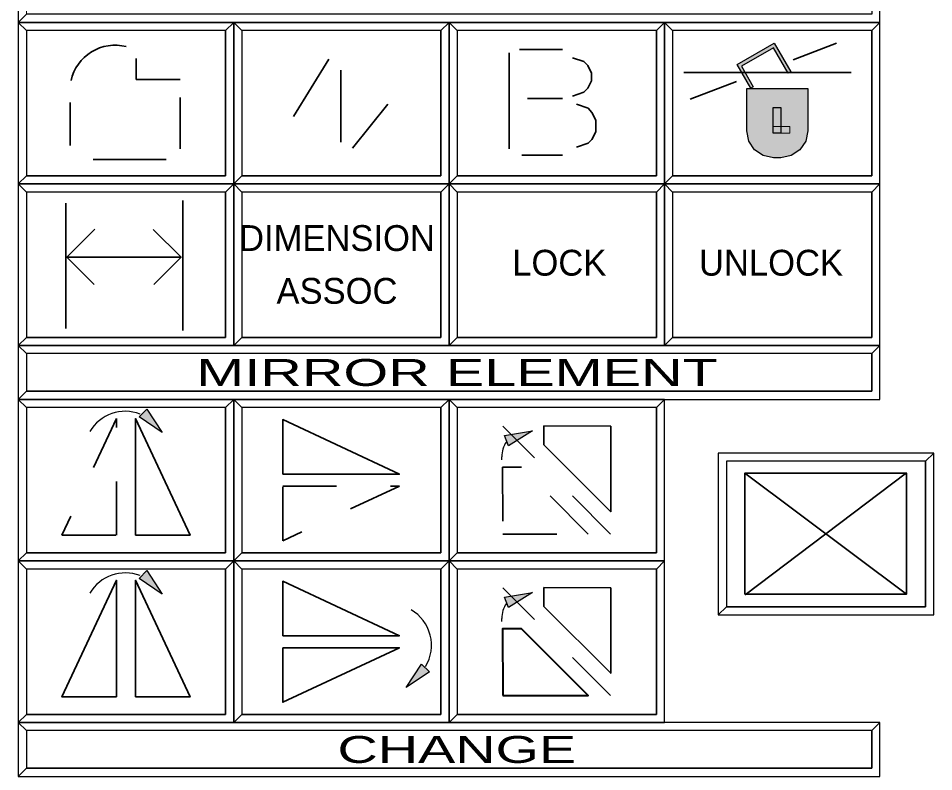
# Model space of a CAD drawing. Extents: x 95906.9 to 95918.9, y 90964.8 to 90972.9.
# Drawn here: x 95912.632 to 95914.332, y 90965.47 to 90966.869 of the extents above; entities that cross this region are included whole.
import ezdxf
from ezdxf.enums import TextEntityAlignment as Align

# ---------------------------------------------------------------- set-up
doc = ezdxf.new("R2010")
doc.units = 0
doc.header["$LTSCALE"] = 0.019
doc.linetypes.add('MEDIUM_DASHED', pattern=[4.5, 3, -1.5])
for name, color, linetype, lineweight in [('1', 7, 'Continuous', 25), ('11', 7, 'Continuous', 25), ('12', 7, 'Continuous', 25), ('16', 7, 'Continuous', 25), ('18', 7, 'Continuous', 25), ('2', 7, 'Continuous', 13), ('3', 7, 'Continuous', 25), ('4', 7, 'Continuous', 35), ('6', 7, 'Continuous', 35), ('7', 7, 'Continuous', 35)]:
    doc.layers.add(name, color=color, linetype=linetype, lineweight=lineweight)

msp = doc.modelspace()

# ---------------------------------------------------------------- hatches: boundary and pattern name
at = {"layer": '6'}
for points in [[(95913.9928, 90966.7395), (95913.9675, 90966.7833), (95914.0361, 90966.8229), (95914.0668, 90966.7698), (95914.0621, 90966.7671), (95914.0349, 90966.8145), (95913.9753, 90966.7803), (95913.9973, 90966.7421)], [(95913.985, 90966.6604), (95913.985, 90966.7388), (95914.0985, 90966.7388), (95914.0985, 90966.6604), (95914.0947, 90966.6413), (95914.0839, 90966.625), (95914.0676, 90966.6142), (95914.0485, 90966.6104), (95914.035, 90966.6104), (95914.0159, 90966.6142), (95913.9996, 90966.625), (95913.9888, 90966.6413)], [(95914.034, 90966.7039), (95914.0482, 90966.7039), (95914.0482, 90966.6558), (95914.034, 90966.6558)], [(95914.034, 90966.6558), (95914.0653, 90966.6558), (95914.0653, 90966.6683), (95914.034, 90966.6683)], [(95912.8712, 90966.1437), (95912.8997, 90966.0999), (95912.8566, 90966.1294)], [(95913.5355, 90966.0945), (95913.587, 90966.1032), (95913.5428, 90966.0755)], [(95912.8712, 90965.8437), (95912.8997, 90965.7999), (95912.8566, 90965.8294)], [(95913.5355, 90965.7945), (95913.587, 90965.8032), (95913.5428, 90965.7755)], [(95913.3959, 90965.656), (95913.3528, 90965.6265), (95913.3813, 90965.6702)]]:
    msp.add_hatch(color=256, dxfattribs=at).paths.add_polyline_path(points)

# ---------------------------------------------------------------- linework, layer by layer
at = {"layer": '1'}
for points in [[(95912.6323, 90966.8617), (95914.2323, 90966.8617), (95914.2323, 90966.9617), (95912.6323, 90966.9617)], [(95912.6323, 90966.5617), (95913.0323, 90966.5617), (95913.0323, 90966.8617), (95912.6323, 90966.8617)], [(95913.0323, 90966.5617), (95913.4323, 90966.5617), (95913.4323, 90966.8617), (95913.0323, 90966.8617)], [(95913.4323, 90966.5617), (95913.8323, 90966.5617), (95913.8323, 90966.8617), (95913.4323, 90966.8617)], [(95913.8323, 90966.5617), (95914.2323, 90966.5617), (95914.2323, 90966.8617), (95913.8323, 90966.8617)], [(95912.6323, 90966.2617), (95913.0323, 90966.2617), (95913.0323, 90966.5617), (95912.6323, 90966.5617)], [(95913.0323, 90966.2617), (95913.4323, 90966.2617), (95913.4323, 90966.5617), (95913.0323, 90966.5617)], [(95913.4323, 90966.2617), (95913.8323, 90966.2617), (95913.8323, 90966.5617), (95913.4323, 90966.5617)], [(95913.8323, 90966.2617), (95914.2323, 90966.2617), (95914.2323, 90966.5617), (95913.8323, 90966.5617)], [(95912.6323, 90966.1617), (95914.2323, 90966.1617), (95914.2323, 90966.2617), (95912.6323, 90966.2617)], [(95912.6323, 90965.8617), (95913.0323, 90965.8617), (95913.0323, 90966.1617), (95912.6323, 90966.1617)], [(95913.0323, 90965.8617), (95913.4323, 90965.8617), (95913.4323, 90966.1617), (95913.0323, 90966.1617)], [(95913.4323, 90965.8617), (95913.8323, 90965.8617), (95913.8323, 90966.1617), (95913.4323, 90966.1617)], [(95913.9323, 90965.7617), (95914.3323, 90965.7617), (95914.3323, 90966.0617), (95913.9323, 90966.0617)], [(95912.6323, 90965.5617), (95913.0323, 90965.5617), (95913.0323, 90965.8617), (95912.6323, 90965.8617)], [(95913.0323, 90965.5617), (95913.4323, 90965.5617), (95913.4323, 90965.8617), (95913.0323, 90965.8617)], [(95913.4323, 90965.5617), (95913.8323, 90965.5617), (95913.8323, 90965.8617), (95913.4323, 90965.8617)], [(95912.6323, 90965.4617), (95914.2323, 90965.4617), (95914.2323, 90965.5617), (95912.6323, 90965.5617)]]:
    msp.add_lwpolyline(points, close=True, dxfattribs=at)
at = {"layer": '11'}
for points in [[(95912.6473, 90966.5767), (95913.0173, 90966.5767), (95913.0173, 90966.8467), (95912.6473, 90966.8467)], [(95913.0473, 90966.5767), (95913.4173, 90966.5767), (95913.4173, 90966.8467), (95913.0473, 90966.8467)], [(95913.4473, 90966.5767), (95913.8173, 90966.5767), (95913.8173, 90966.8467), (95913.4473, 90966.8467)], [(95913.8473, 90966.5767), (95914.2173, 90966.5767), (95914.2173, 90966.8467), (95913.8473, 90966.8467)], [(95912.6473, 90966.2767), (95913.0173, 90966.2767), (95913.0173, 90966.5467), (95912.6473, 90966.5467)], [(95913.0473, 90966.2767), (95913.4173, 90966.2767), (95913.4173, 90966.5467), (95913.0473, 90966.5467)], [(95913.4473, 90966.2767), (95913.8173, 90966.2767), (95913.8173, 90966.5467), (95913.4473, 90966.5467)], [(95913.8473, 90966.2767), (95914.2173, 90966.2767), (95914.2173, 90966.5467), (95913.8473, 90966.5467)], [(95912.6473, 90965.8767), (95913.0173, 90965.8767), (95913.0173, 90966.1467), (95912.6473, 90966.1467)], [(95913.0473, 90965.8767), (95913.4173, 90965.8767), (95913.4173, 90966.1467), (95913.0473, 90966.1467)], [(95913.4473, 90965.8767), (95913.8173, 90965.8767), (95913.8173, 90966.1467), (95913.4473, 90966.1467)], [(95912.6473, 90965.5767), (95913.0173, 90965.5767), (95913.0173, 90965.8467), (95912.6473, 90965.8467)], [(95913.0473, 90965.5767), (95913.4173, 90965.5767), (95913.4173, 90965.8467), (95913.0473, 90965.8467)], [(95913.4473, 90965.5767), (95913.8173, 90965.5767), (95913.8173, 90965.8467), (95913.4473, 90965.8467)]]:
    msp.add_lwpolyline(points, close=True, dxfattribs=at)
at = {"layer": '12'}
for points in [[(95912.6473, 90966.5767), (95913.0173, 90966.5767), (95913.0173, 90966.8467), (95912.6473, 90966.8467)], [(95912.6473, 90965.8767), (95913.0173, 90965.8767), (95913.0173, 90966.1467), (95912.6473, 90966.1467)]]:
    msp.add_lwpolyline(points, close=True, dxfattribs=at)
at = {"layer": '16'}
msp.add_lwpolyline([(95913.9473, 90965.7767), (95914.3173, 90965.7767), (95914.3173, 90966.0467), (95913.9473, 90966.0467)], close=True, dxfattribs=at)
msp.add_lwpolyline([(95913.9473, 90965.7767), (95914.3173, 90965.7767), (95914.3173, 90966.0467), (95913.9473, 90966.0467)], close=True, dxfattribs=at)
at = {"layer": '18'}
for points in [[(95912.6473, 90966.1767), (95914.2173, 90966.1767), (95914.2173, 90966.2467), (95912.6473, 90966.2467)], [(95912.6473, 90965.4767), (95914.2173, 90965.4767), (95914.2173, 90965.5467), (95912.6473, 90965.5467)]]:
    msp.add_lwpolyline(points, close=True, dxfattribs=at)
at = {"layer": '2'}
for points in [[(95912.6323, 90966.9617), (95912.6323, 90966.8617), (95912.6473, 90966.8767), (95912.6473, 90966.9467), (95914.2173, 90966.9467), (95914.2323, 90966.9617)], [(95912.6323, 90966.8617), (95912.6323, 90966.5617), (95912.6473, 90966.5767), (95912.6473, 90966.8467), (95913.0173, 90966.8467), (95913.0323, 90966.8617)], [(95913.0323, 90966.8617), (95913.0323, 90966.5617), (95913.0473, 90966.5767), (95913.0473, 90966.8467), (95913.4173, 90966.8467), (95913.4323, 90966.8617)], [(95913.4323, 90966.8617), (95913.4323, 90966.5617), (95913.4473, 90966.5767), (95913.4473, 90966.8467), (95913.8173, 90966.8467), (95913.8323, 90966.8617)], [(95913.8323, 90966.8617), (95913.8323, 90966.5617), (95913.8473, 90966.5767), (95913.8473, 90966.8467), (95914.2173, 90966.8467), (95914.2323, 90966.8617)], [(95912.6323, 90966.5617), (95912.6323, 90966.2617), (95912.6473, 90966.2767), (95912.6473, 90966.5467), (95913.0173, 90966.5467), (95913.0323, 90966.5617)], [(95913.0323, 90966.5617), (95913.0323, 90966.2617), (95913.0473, 90966.2767), (95913.0473, 90966.5467), (95913.4173, 90966.5467), (95913.4323, 90966.5617)], [(95913.4323, 90966.5617), (95913.4323, 90966.2617), (95913.4473, 90966.2767), (95913.4473, 90966.5467), (95913.8173, 90966.5467), (95913.8323, 90966.5617)], [(95913.8323, 90966.5617), (95913.8323, 90966.2617), (95913.8473, 90966.2767), (95913.8473, 90966.5467), (95914.2173, 90966.5467), (95914.2323, 90966.5617)], [(95912.6323, 90966.2617), (95912.6323, 90966.1617), (95912.6473, 90966.1767), (95912.6473, 90966.2467), (95914.2173, 90966.2467), (95914.2323, 90966.2617)], [(95912.6323, 90966.1617), (95912.6323, 90965.8617), (95912.6473, 90965.8767), (95912.6473, 90966.1467), (95913.0173, 90966.1467), (95913.0323, 90966.1617)], [(95913.0323, 90966.1617), (95913.0323, 90965.8617), (95913.0473, 90965.8767), (95913.0473, 90966.1467), (95913.4173, 90966.1467), (95913.4323, 90966.1617)], [(95913.4323, 90966.1617), (95913.4323, 90965.8617), (95913.4473, 90965.8767), (95913.4473, 90966.1467), (95913.8173, 90966.1467), (95913.8323, 90966.1617)], [(95913.9323, 90966.0617), (95913.9323, 90965.7617), (95913.9473, 90965.7767), (95913.9473, 90966.0467), (95914.3173, 90966.0467), (95914.3323, 90966.0617)], [(95912.6323, 90965.8617), (95912.6323, 90965.5617), (95912.6473, 90965.5767), (95912.6473, 90965.8467), (95913.0173, 90965.8467), (95913.0323, 90965.8617)], [(95913.0323, 90965.8617), (95913.0323, 90965.5617), (95913.0473, 90965.5767), (95913.0473, 90965.8467), (95913.4173, 90965.8467), (95913.4323, 90965.8617)], [(95913.4323, 90965.8617), (95913.4323, 90965.5617), (95913.4473, 90965.5767), (95913.4473, 90965.8467), (95913.8173, 90965.8467), (95913.8323, 90965.8617)], [(95912.6323, 90965.5617), (95912.6323, 90965.4617), (95912.6473, 90965.4767), (95912.6473, 90965.5467), (95914.2173, 90965.5467), (95914.2323, 90965.5617)]]:
    msp.add_lwpolyline(points, close=True, dxfattribs=at)
at = {"layer": '3'}
for points in [[(95912.6323, 90966.8617), (95914.2323, 90966.8617), (95914.2323, 90966.9617), (95914.2173, 90966.9467), (95914.2173, 90966.8767), (95912.6473, 90966.8767)], [(95912.6323, 90966.5617), (95913.0323, 90966.5617), (95913.0323, 90966.8617), (95913.0173, 90966.8467), (95913.0173, 90966.5767), (95912.6473, 90966.5767)], [(95913.0323, 90966.5617), (95913.4323, 90966.5617), (95913.4323, 90966.8617), (95913.4173, 90966.8467), (95913.4173, 90966.5767), (95913.0473, 90966.5767)], [(95913.4323, 90966.5617), (95913.8323, 90966.5617), (95913.8323, 90966.8617), (95913.8173, 90966.8467), (95913.8173, 90966.5767), (95913.4473, 90966.5767)], [(95913.8323, 90966.5617), (95914.2323, 90966.5617), (95914.2323, 90966.8617), (95914.2173, 90966.8467), (95914.2173, 90966.5767), (95913.8473, 90966.5767)], [(95912.6323, 90966.2617), (95913.0323, 90966.2617), (95913.0323, 90966.5617), (95913.0173, 90966.5467), (95913.0173, 90966.2767), (95912.6473, 90966.2767)], [(95913.0323, 90966.2617), (95913.4323, 90966.2617), (95913.4323, 90966.5617), (95913.4173, 90966.5467), (95913.4173, 90966.2767), (95913.0473, 90966.2767)], [(95913.4323, 90966.2617), (95913.8323, 90966.2617), (95913.8323, 90966.5617), (95913.8173, 90966.5467), (95913.8173, 90966.2767), (95913.4473, 90966.2767)], [(95913.8323, 90966.2617), (95914.2323, 90966.2617), (95914.2323, 90966.5617), (95914.2173, 90966.5467), (95914.2173, 90966.2767), (95913.8473, 90966.2767)], [(95912.6323, 90966.1617), (95914.2323, 90966.1617), (95914.2323, 90966.2617), (95914.2173, 90966.2467), (95914.2173, 90966.1767), (95912.6473, 90966.1767)], [(95912.6323, 90965.8617), (95913.0323, 90965.8617), (95913.0323, 90966.1617), (95913.0173, 90966.1467), (95913.0173, 90965.8767), (95912.6473, 90965.8767)], [(95913.0323, 90965.8617), (95913.4323, 90965.8617), (95913.4323, 90966.1617), (95913.4173, 90966.1467), (95913.4173, 90965.8767), (95913.0473, 90965.8767)], [(95913.4323, 90965.8617), (95913.8323, 90965.8617), (95913.8323, 90966.1617), (95913.8173, 90966.1467), (95913.8173, 90965.8767), (95913.4473, 90965.8767)], [(95913.9323, 90965.7617), (95914.3323, 90965.7617), (95914.3323, 90966.0617), (95914.3173, 90966.0467), (95914.3173, 90965.7767), (95913.9473, 90965.7767)], [(95912.6323, 90965.5617), (95913.0323, 90965.5617), (95913.0323, 90965.8617), (95913.0173, 90965.8467), (95913.0173, 90965.5767), (95912.6473, 90965.5767)], [(95913.0323, 90965.5617), (95913.4323, 90965.5617), (95913.4323, 90965.8617), (95913.4173, 90965.8467), (95913.4173, 90965.5767), (95913.0473, 90965.5767)], [(95913.4323, 90965.5617), (95913.8323, 90965.5617), (95913.8323, 90965.8617), (95913.8173, 90965.8467), (95913.8173, 90965.5767), (95913.4473, 90965.5767)], [(95912.6323, 90965.4617), (95914.2323, 90965.4617), (95914.2323, 90965.5617), (95914.2173, 90965.5467), (95914.2173, 90965.4767), (95912.6473, 90965.4767)]]:
    msp.add_lwpolyline(points, close=True, dxfattribs=at)
at = {"layer": '4'}
for p, q in [((95912.6473, 90966.8467), (95912.6323, 90966.8617)), ((95913.0473, 90966.8467), (95913.0323, 90966.8617)), ((95913.4473, 90966.8467), (95913.4323, 90966.8617)), ((95913.8473, 90966.8467), (95913.8323, 90966.8617)), ((95912.6473, 90966.5467), (95912.6323, 90966.5617)), ((95913.0473, 90966.5467), (95913.0323, 90966.5617)), ((95913.4473, 90966.5467), (95913.4323, 90966.5617)), ((95913.8473, 90966.5467), (95913.8323, 90966.5617)), ((95912.6473, 90966.2467), (95912.6323, 90966.2617)), ((95912.6473, 90966.1467), (95912.6323, 90966.1617)), ((95913.0473, 90966.1467), (95913.0323, 90966.1617)), ((95913.4473, 90966.1467), (95913.4323, 90966.1617)), ((95912.6473, 90965.8467), (95912.6323, 90965.8617)), ((95913.0473, 90965.8467), (95913.0323, 90965.8617)), ((95913.4473, 90965.8467), (95913.4323, 90965.8617)), ((95912.6473, 90965.5467), (95912.6323, 90965.5617))]:
    msp.add_line(p, q, dxfattribs=at)
at = {"layer": '6'}
for p, q in [((95914.1519, 90966.8228), (95914.0715, 90966.7921)), ((95913.5441, 90966.8053), (95913.5441, 90966.6271)), ((95913.5631, 90966.8114), (95913.643, 90966.8114)), ((95913.1434, 90966.687), (95913.2087, 90966.7935)), ((95913.231, 90966.6393), (95913.231, 90966.773)), ((95913.8683, 90966.7685), (95914.179, 90966.7685)), ((95913.8802, 90966.7192), (95913.966, 90966.7519)), ((95912.7284, 90966.6332), (95912.7284, 90966.7131)), ((95912.9328, 90966.7223), (95912.9328, 90966.627)), ((95913.5779, 90966.7203), (95913.643, 90966.7203)), ((95913.3186, 90966.71), (95913.2531, 90966.6284)), ((95913.643, 90966.6149), (95913.5677, 90966.6149)), ((95912.9067, 90966.6071), (95912.7714, 90966.6071)), ((95912.7206, 90966.5257), (95912.7206, 90966.2931)), ((95912.9379, 90966.5308), (95912.9379, 90966.2897)), ((95912.7223, 90966.4255), (95912.7747, 90966.4779)), ((95912.7223, 90966.4255), (95912.773, 90966.3747)), ((95912.9345, 90966.4255), (95912.8842, 90966.3752)), ((95913.9815, 90966.0248), (95914.2815, 90965.7998)), ((95913.9823, 90965.7989), (95914.2815, 90966.0251))]:
    msp.add_line(p, q, dxfattribs=at)
at = {"layer": '6', "linetype": 'MEDIUM_DASHED'}
for p, q in [((95913.7323, 90965.9117), (95913.5323, 90966.1117)), ((95913.7323, 90965.6117), (95913.5323, 90965.8117))]:
    msp.add_line(p, q, dxfattribs=at)
at = {"layer": '6', "lineweight": 25}
for p, q in [((95913.5301, 90966.0495), (95913.5301, 90966.0549)), ((95913.5301, 90965.7495), (95913.5301, 90965.7549))]:
    msp.add_line(p, q, dxfattribs=at)
for points in [[(95913.9928, 90966.7395), (95913.9675, 90966.7833), (95914.0361, 90966.8229), (95914.0668, 90966.7698), (95914.0621, 90966.7671), (95914.0349, 90966.8145), (95913.9753, 90966.7803), (95913.9973, 90966.7421)], [(95913.985, 90966.6604), (95913.985, 90966.7388), (95914.0985, 90966.7388), (95914.0985, 90966.6604), (95914.0947, 90966.6413), (95914.0839, 90966.625), (95914.0676, 90966.6142), (95914.0485, 90966.6104), (95914.035, 90966.6104), (95914.0159, 90966.6142), (95913.9996, 90966.625), (95913.9888, 90966.6413)], [(95914.034, 90966.7039), (95914.0482, 90966.7039), (95914.0482, 90966.6558), (95914.034, 90966.6558)], [(95912.8712, 90966.1437), (95912.8997, 90966.0999), (95912.8566, 90966.1294)], [(95913.5355, 90966.0945), (95913.587, 90966.1032), (95913.5428, 90966.0755)], [(95912.8712, 90965.8437), (95912.8997, 90965.7999), (95912.8566, 90965.8294)], [(95913.5355, 90965.7945), (95913.587, 90965.8032), (95913.5428, 90965.7755)], [(95913.3959, 90965.656), (95913.3528, 90965.6265), (95913.3813, 90965.6702)]]:
    msp.add_lwpolyline(points, close=True, dxfattribs=at)
at = {"layer": '6'}
for points in [[(95913.6614, 90966.796), (95913.6828, 90966.7889), (95913.6899, 90966.7818), (95913.697, 90966.7676), (95913.697, 90966.7534), (95913.6899, 90966.7392), (95913.6828, 90966.7321), (95913.6614, 90966.7249)], [(95912.9328, 90966.7557), (95912.8513, 90966.7557), (95912.8513, 90966.7946)], [(95913.6691, 90966.7095), (95913.6905, 90966.7024), (95913.6976, 90966.6941), (95913.7047, 90966.6799), (95913.7047, 90966.6586), (95913.6976, 90966.6444), (95913.6905, 90966.6373), (95913.6691, 90966.6302)], [(95912.7223, 90966.4255), (95912.9345, 90966.4255), (95912.883, 90966.477)]]:
    msp.add_lwpolyline(points, dxfattribs=at)
at = {"layer": '6', "lineweight": 13}
msp.add_lwpolyline([(95914.034, 90966.6558), (95914.0653, 90966.6558), (95914.0653, 90966.6683), (95914.034, 90966.6683)], close=True, dxfattribs=at)
at = {"layer": '6', "linetype": 'MEDIUM_DASHED'}
for points in [[(95912.8146, 90965.9093), (95912.8146, 90966.126), (95912.7132, 90965.9093)], [(95913.5323, 90965.9117), (95913.6909, 90965.9117), (95913.567, 90966.0356), (95913.5317, 90966.0356)], [(95913.1234, 90966.0007), (95913.3401, 90966.0007), (95913.1234, 90965.8993)]]:
    msp.add_lwpolyline(points, close=True, dxfattribs=at)
at = {"layer": '6'}
for points in [[(95912.85, 90965.9093), (95912.85, 90966.126), (95912.9514, 90965.9093)], [(95913.1234, 90966.0227), (95913.3401, 90966.0227), (95913.1234, 90966.1241)], [(95913.7324, 90966.1118), (95913.7324, 90965.9532), (95913.6085, 90966.0771), (95913.6085, 90966.1124)], [(95913.9816, 90965.7999), (95914.2816, 90965.7999), (95914.2816, 90966.0249), (95913.9816, 90966.0249)], [(95912.8146, 90965.6093), (95912.8146, 90965.826), (95912.7132, 90965.6093)], [(95912.85, 90965.6093), (95912.85, 90965.826), (95912.9514, 90965.6093)], [(95913.1234, 90965.7227), (95913.3401, 90965.7227), (95913.1234, 90965.8241)], [(95913.7324, 90965.8118), (95913.7324, 90965.6532), (95913.6085, 90965.7771), (95913.6085, 90965.8124)], [(95913.1234, 90965.7007), (95913.3401, 90965.7007), (95913.1234, 90965.5993)]]:
    msp.add_lwpolyline(points, close=True, dxfattribs=at)
at = {"layer": '6', "lineweight": 40}
msp.add_lwpolyline([(95913.5323, 90965.6117), (95913.6909, 90965.6117), (95913.567, 90965.7356), (95913.5317, 90965.7356)], close=True, dxfattribs=at)
at = {"layer": '6'}
msp.add_arc((95912.8121, 90966.7354), 0.0838, 75.8303, 167.4043, dxfattribs=at)
at = {"layer": '6', "lineweight": 25}
for centre, radius, start, end in [((95912.8311, 90966.0628), 0.0767, 69.0308, 149.3662), ((95913.5801, 90966.0549), 0.05, 145.9676, 180), ((95912.8311, 90965.7628), 0.0767, 69.0308, 149.3662), ((95913.5801, 90965.7549), 0.05, 145.9676, 180), ((95913.3229, 90965.705), 0.0767, 329.1884, 59.3661)]:
    msp.add_arc(centre, radius, start, end, dxfattribs=at)

# ---------------------------------------------------------------- texts
at = {"layer": '6'}
for s, p in [('DIMENSION', (95913.2241, 90966.4372)), ('LOCK', (95913.637, 90966.3914)), ('UNLOCK', (95914.0302, 90966.3914)), ('ASSOC', (95913.2241, 90966.3392))]:
    msp.add_text(s, height=0.048, dxfattribs=at).set_placement(p, align=Align.CENTER)
at = {"layer": '7'}
for s, width, p in [('     MIRROR ELEMENT    ', 1.6, (95913.4322, 90966.1867)), ('         CHANGE        ', 1.55, (95913.4323, 90965.4867))]:
    msp.add_text(s, height=0.04999, dxfattribs=dict(at, width=width)).set_placement(p, align=Align.CENTER)

doc.saveas('drawing.dxf')
